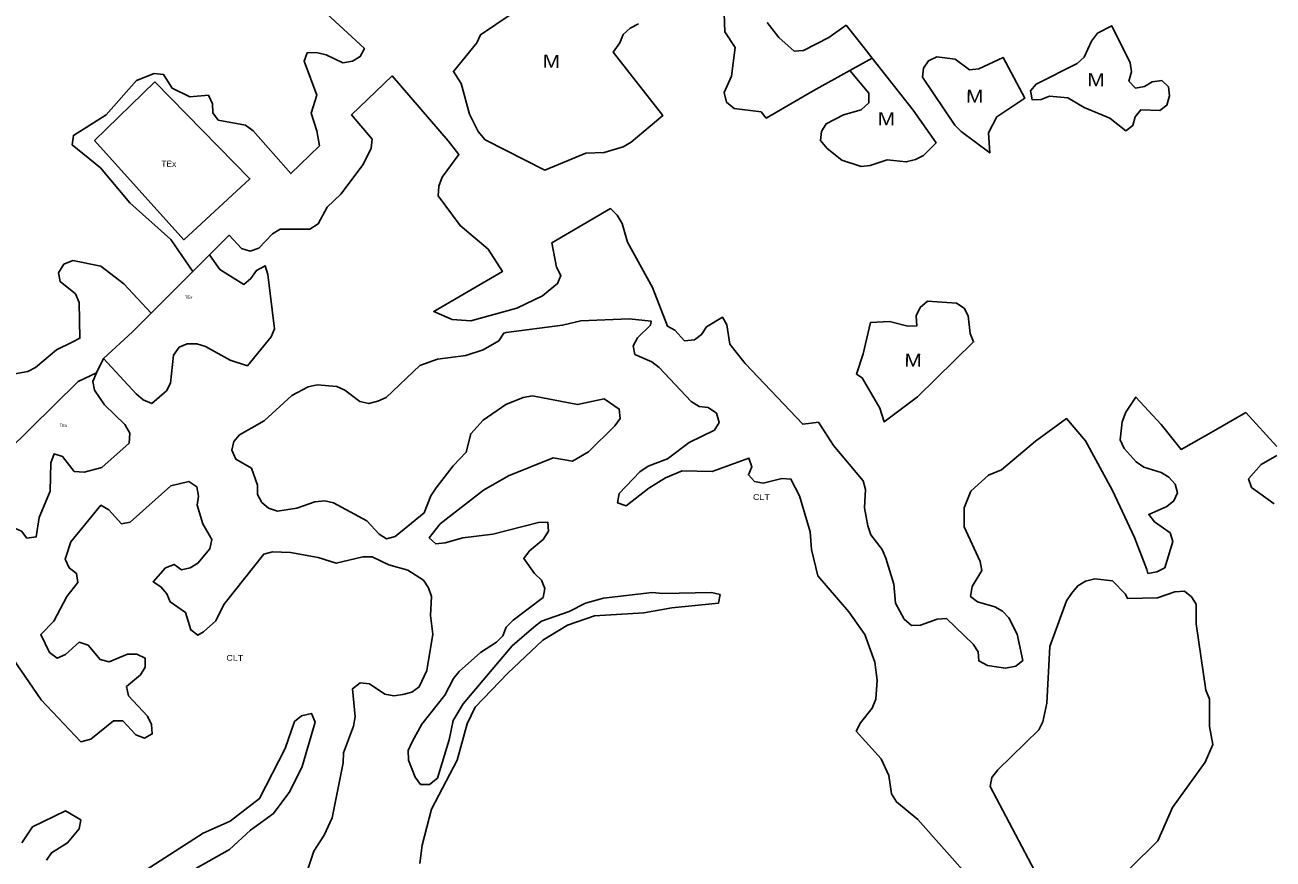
# Model space of a CAD drawing. Extents: x 713589 to 726391, y 7177764 to 7191819.
# Drawn here: x 717161 to 718159, y 7179535 to 7180202 of the extents above; entities that cross this region are included whole.
import ezdxf
from ezdxf.enums import TextEntityAlignment as Align

# ---------------------------------------------------------------- set-up
doc = ezdxf.new("R2010")
doc.units = 0
doc.header["$LTSCALE"] = 2.6
doc.layers.add('63', color=7, linetype='Continuous', lineweight=25)

msp = doc.modelspace()

# ---------------------------------------------------------------- linework, layer by layer
at = {"layer": '63'}
for p, q in [((717838.11, 7180175.6), (717820.18, 7180165.69)), ((717308.17, 7180018.29), (717294.81, 7180004.94)), ((717217.73, 7179923.86), (717223.34, 7179935.43))]:
    msp.add_line(p, q, dxfattribs=at)
for points in [[(717391.45, 7180220.65), (717432.03, 7180183.18), (717428.63, 7180176.88), (717422.38, 7180173.26), (717414.81, 7180171.94), (717401.32, 7180178.2), (717393.42, 7180180.17), (717386.18, 7180179.84), (717383.88, 7180173.26), (717394.07, 7180145.95), (717389.46, 7180131.47), (717394.07, 7180117.32), (717395.98, 7180105.47), (717380.55, 7180090.65), (717373.16, 7180083.26), (717343.06, 7180117.33), (717336.81, 7180121.94), (717315.09, 7180125.89), (717310.82, 7180131.81), (717310.49, 7180139.05), (717307.2, 7180145.96), (717292.39, 7180144.65), (717278.25, 7180151.61), (717271.33, 7180162.42), (717263.76, 7180163.41), (717249.61, 7180157.82), (717225.59, 7180130.18), (717199.26, 7180113.73), (717198.27, 7180106.17), (717220.97, 7180087.73), (717244.33, 7180059.76), (717277.23, 7180030.47), (717294.81, 7180004.94)], [(717549.45, 7180210.74), (717524.83, 7180194.33), (717521.87, 7180187.77), (717503.27, 7180164.85), (717509.29, 7180155.28), (717516.14, 7180130.79), (717522.95, 7180117.05), (717528.65, 7180110.22), (717576.22, 7180085.99), (717609.16, 7180099.47), (717623.92, 7180100.13), (717639.02, 7180104.72), (717645.26, 7180108.33), (717670.74, 7180129.82), (717631.07, 7180180.46), (717636.41, 7180187.75), (717639.04, 7180194.64), (717644.62, 7180199.56), (717651.18, 7180203.17)], [(717719.77, 7180211.37), (717720.43, 7180196.6), (717728.63, 7180184.12), (717725.67, 7180161.15), (717719.76, 7180148.03), (717721.73, 7180140.48), (717727.64, 7180135.23), (717749.3, 7180132.6), (717753.3, 7180127.63), (717790.85, 7180149.48), (717820.18, 7180165.69)], [(717838.11, 7180175.6), (717831.7, 7180183.73), (717817.32, 7180201.97), (717803.46, 7180191.99), (717783.11, 7180181.82), (717775.89, 7180181.16), (717763.42, 7180192), (717754.23, 7180204.14)], [(717820.18, 7180165.69), (717835.61, 7180147.68), (717835.61, 7180139.8), (717829.37, 7180134.22), (717815.26, 7180130.29), (717801.47, 7180123.07), (717797.54, 7180116.84), (717796.88, 7180109.62), (717802.13, 7180103.38), (717813.94, 7180093.86), (717829.36, 7180088.93), (717836.58, 7180089.59), (717850.04, 7180094.18), (717865.47, 7180092.54), (717872.69, 7180094.51), (717879.25, 7180097.79), (717889.31, 7180107.88), (717870.9, 7180134.02), (717838.11, 7180175.6)], [(717308.17, 7180018.29), (717323.83, 7180033.95), (717333.83, 7180023.28), (717340.74, 7180021.31), (717347.65, 7180023.61), (717358.52, 7180035.12), (717364.77, 7180038.74), (717388.46, 7180038.74), (717395.04, 7180043.02), (717402.29, 7180056.51), (717413.15, 7180066.71), (717430.92, 7180090.4), (717437.5, 7180103.56), (717438.16, 7180110.8), (717421.74, 7180130.2), (717454.2, 7180161.37), (717498.95, 7180109.38), (717507.66, 7180098.55), (717494.1, 7180080.51), (717491.47, 7180073.27), (717491.14, 7180065.38), (717508.57, 7180041.68), (717530.95, 7180022.92), (717542.38, 7180004.89), (717487.5, 7179972.96), (717502.31, 7179966.65), (717517.12, 7179965.33), (717553.97, 7179975.53), (717574.38, 7179985.4), (717586.55, 7179995.27), (717589.19, 7180001.85), (717585.57, 7180008.43), (717581.99, 7180027.94), (717628.85, 7180055.21), (717634.29, 7180049.88), (717638.16, 7180043.24), (717642.46, 7180028.26), (717662.39, 7179992.25), (717674.4, 7179961.11), (717680.38, 7179957.99), (717688.12, 7179949.47), (717696.1, 7179950.14), (717701.68, 7179954.4), (717705.62, 7179960.64), (717718.42, 7179968.51), (717722.03, 7179962.27), (717724.32, 7179946.85), (717734.53, 7179933.88), (717736.47, 7179931.41), (717782.66, 7179882.69), (717789.34, 7179883.57), (717795.17, 7179884.33), (717807.34, 7179865.77), (717830.96, 7179837.54), (717832.93, 7179830.65), (717831.94, 7179815.88), (717834.56, 7179801.44), (717837.19, 7179794.22), (717846.05, 7179782.41), (717849, 7179775.52), (717855.56, 7179754.84), (717856.87, 7179739.74), (717863.76, 7179726.94), (717869.67, 7179721.69), (717876.89, 7179722.02), (717890.01, 7179726.94), (717897.56, 7179727.26), (717918.89, 7179706.91), (717922.83, 7179700.68), (717923.48, 7179693.46), (717930.37, 7179689.84), (717944.81, 7179687.55), (717953.02, 7179689.18), (717958.6, 7179693.78), (717954.01, 7179714.78), (717947.45, 7179727.91), (717942.53, 7179733.16), (717936.29, 7179736.77), (717922.51, 7179740.71), (717916.93, 7179744.98), (717918.24, 7179752.86), (717925.79, 7179765.66), (717924.48, 7179772.88), (717911.69, 7179800.77), (717911.69, 7179815.87), (717916.94, 7179829.33), (717931.31, 7179842.11), (717941.6, 7179846.14), (717968.91, 7179869.26), (717993.63, 7179887.23), (718008.73, 7179869.49), (718030.44, 7179829.67), (718047.88, 7179792.15), (718057.74, 7179766.48)], [(717261.43, 7179971.57), (717239.71, 7179994.93), (717221.29, 7180009.09), (717198.91, 7180013.7), (717191.67, 7180010.74), (717187.39, 7180003.83), (717188.71, 7179996.92), (717200.88, 7179987.04), (717203.84, 7179980.13), (717204.45, 7179951.5), (717198.3, 7179948.47), (717185.71, 7179942.28), (717168.93, 7179928.13), (717162.68, 7179924.84), (717140.63, 7179920.89)], [(717223.34, 7179935.43), (717249.57, 7179907.13), (717255.16, 7179902.2), (717262.07, 7179899.23), (717273.59, 7179909.43), (717276.89, 7179915.69), (717279.19, 7179938.06), (717283.8, 7179944.31), (717290.38, 7179946.95), (717297.95, 7179946.94), (717304.86, 7179944.97), (717324.6, 7179934.11), (717338.42, 7179929.5), (717357.51, 7179952.53), (717360.15, 7179959.11), (717354.89, 7180002.55), (717352.59, 7180009.46), (717345.68, 7180005.84), (717341.07, 7179999.26), (717335.47, 7179994.65), (717316.39, 7180006.5), (717308.17, 7180018.29)], [(717294.81, 7180004.94), (717285.34, 7179995.47), (717261.43, 7179971.57)], [(717261.43, 7179971.57), (717246.59, 7179956.74), (717223.34, 7179935.43)], [(717713.56, 7179891.59), (717706.98, 7179896.2), (717699.74, 7179896.85), (717693.49, 7179900.8), (717667.82, 7179928.12), (717661.9, 7179932.73), (717648.41, 7179938.66), (717647.09, 7179945.57), (717650.39, 7179951.82), (717660.92, 7179962.02), (717661.38, 7179965.21), (717643.87, 7179966.98), (717605.2, 7179965.59), (717590.48, 7179961.92), (717545.52, 7179956.15), (717543.42, 7179955.56), (717539.49, 7179949.53), (717526.98, 7179942.3), (717513.16, 7179937.69), (717490.46, 7179934.73), (717476.3, 7179929.8), (717449.32, 7179904.14), (717442.73, 7179901.18), (717435.49, 7179899.2), (717428.25, 7179900.85), (717416.41, 7179910.07), (717409.83, 7179913.03), (717394.36, 7179914.35), (717387.12, 7179912.7), (717373.96, 7179905.8), (717351.91, 7179885.4), (717332.16, 7179874.21), (717327.55, 7179868.95), (717325.91, 7179862.04), (717329.2, 7179854.8), (717341.7, 7179847.56), (717346.63, 7179834.06), (717346.63, 7179826.5), (717349.92, 7179820.24), (717355.19, 7179815.63), (717362.43, 7179813.33), (717377.89, 7179815.63), (717392.37, 7179820.56), (717400.27, 7179821.55), (717407.18, 7179819.9), (717433.83, 7179805.42), (717443.7, 7179794.89), (717449.63, 7179790.94), (717456.54, 7179792.91), (717479.9, 7179811.99), (717485.17, 7179825.48), (717489.45, 7179831.74), (717502.94, 7179849.5), (717513.48, 7179860.36), (717517.1, 7179875.17), (717526.97, 7179886.03), (717545.07, 7179898.53), (717558.9, 7179904.12), (717566.47, 7179905.43), (717602.33, 7179898.52), (717623.72, 7179903.12), (717635.9, 7179894.89), (717636.55, 7179887.32), (717632.28, 7179881.4), (717611.21, 7179860.67), (717598.38, 7179853.11), (717582.91, 7179855.74), (717547.37, 7179841.6), (717527.29, 7179830.08), (717492.74, 7179803.11), (717483.85, 7179791.92), (717489.11, 7179786.98), (717496.68, 7179787.97), (717510.83, 7179791.91), (717534.86, 7179794.87), (717571.38, 7179804.08), (717578.62, 7179804.41), (717579.28, 7179797.17), (717575, 7179790.59), (717564.14, 7179781.37), (717559.53, 7179775.45), (717568.09, 7179763.27), (717573.68, 7179758.01), (717576.31, 7179751.43), (717574.99, 7179744.19), (717550.97, 7179726.09), (717545.37, 7179720.5), (717542.74, 7179713.59), (717537.8, 7179708.33), (717524.97, 7179700.1), (717507.85, 7179684.97), (717503.24, 7179679.37), (717496.33, 7179665.88), (717477.9, 7179642.85), (717470.33, 7179628.7)], [(717217.73, 7179923.86), (717203.15, 7179916.93), (717145.88, 7179860.67), (717045.83, 7179761.97), (717045.8, 7179761.94), (717012.13, 7179728.72), (717014.24, 7179726.64)], [(717146.63, 7179795.56), (717150.5, 7179800.53), (717157.74, 7179797.24), (717162.02, 7179791.65), (717169.59, 7179792.63), (717171.89, 7179808.1), (717180.78, 7179829.16), (717181.11, 7179851.86), (717183.75, 7179859.1), (717190.66, 7179856.8), (717199.87, 7179844.95), (717207.77, 7179844.29), (717221.92, 7179848.24), (717243.97, 7179867.65), (717244.3, 7179875.54), (717240.35, 7179882.46), (717224.23, 7179898.25), (717216.01, 7179910.1), (717214.69, 7179917.01), (717217.73, 7179923.86)], [(718057.74, 7179766.48), (718058.71, 7179763.34), (718065.93, 7179764.65), (718072.16, 7179767.93), (718078.73, 7179788.93), (718076.44, 7179795.82), (718063.97, 7179804.69), (718059.37, 7179810.59), (718073.81, 7179816.83), (718079.39, 7179821.42), (718082.35, 7179827.98), (718080.38, 7179834.88), (718075.46, 7179840.46), (718069.22, 7179844.07), (718055.44, 7179848.34), (718049.21, 7179852.6), (718039.69, 7179863.43), (718036.41, 7179870.33), (718038.05, 7179884.77), (718041.01, 7179892.31), (718049.05, 7179904.46), (718069.42, 7179882.41), (718085.26, 7179862.61), (718111.11, 7179877.3), (718137.01, 7179892.02), (718161.9, 7179865.05)], [(717916.86, 7179519.04), (717874.74, 7179566.44), (717857.64, 7179580.59), (717853.69, 7179587.17), (717851.39, 7179601.65), (717845.47, 7179615.14), (717825.4, 7179637.2), (717828.69, 7179643.78), (717838.23, 7179655.62), (717841.2, 7179662.86), (717842.19, 7179678), (717840.21, 7179692.48), (717832.32, 7179714.53), (717819.49, 7179732.63), (717794.81, 7179761.59), (717789.55, 7179782.65), (717788.57, 7179796.8), (717780.02, 7179825.43), (717773.11, 7179838.93), (717765.87, 7179839.26), (717751.06, 7179835.64), (717744.15, 7179836.96), (717739.22, 7179842.22), (717741.85, 7179848.8), (717739.55, 7179855.71), (717710.26, 7179844.86), (717686.24, 7179845.52), (717672.74, 7179839.93), (717659.58, 7179831.71), (717641.48, 7179817.56), (717634.57, 7179819.86), (717635.89, 7179827.43), (717652.34, 7179844.54), (717658.92, 7179849.15), (717674.39, 7179855.07), (717691.83, 7179868.23), (717711.91, 7179878.1), (717715.86, 7179884.02), (717713.56, 7179891.59)], [(718161.9, 7179857.81), (718149.39, 7179850.57), (718139.19, 7179839.06), (718141.49, 7179832.15), (718159.59, 7179818.98)], [(717147.85, 7179699.51), (717173.51, 7179662.32), (717205.1, 7179628.75), (717213.32, 7179630.72), (717231.43, 7179645.53), (717238.67, 7179645.53), (717249.19, 7179634.34), (717256.1, 7179631.7), (717262.36, 7179634.99), (717261.7, 7179642.56), (717258.41, 7179649.14), (717243.28, 7179665.6), (717241.63, 7179672.84), (717252.82, 7179682.38), (717256.77, 7179688.3), (717256.77, 7179695.54), (717249.86, 7179698.83), (717242.62, 7179698.83), (717227.81, 7179692.58), (717220.58, 7179694.56), (717211.03, 7179706.08), (717203.8, 7179708.38), (717192.93, 7179698.51), (717186.35, 7179695.55), (717180.1, 7179700.16), (717173.19, 7179714.64), (717183.72, 7179725.17), (717193.93, 7179744.91), (717202.82, 7179756.1), (717201.83, 7179763.34), (717195.91, 7179767.95), (717192.62, 7179774.86), (717197.23, 7179788.68), (717221.26, 7179817.96), (717227.51, 7179814.34), (717237.71, 7179803.15), (717244.62, 7179804.47), (717277.2, 7179833.42), (717291.68, 7179837.04), (717297.93, 7179832.76), (717299.25, 7179825.19), (717298.26, 7179817.95), (717302.86, 7179803.14), (717310.1, 7179790.63), (717308.45, 7179783.06), (717298.91, 7179771.55), (717292.65, 7179767.93), (717285.74, 7179766.29), (717279.82, 7179770.57), (717272.91, 7179767.93), (717263.04, 7179756.75), (717269.29, 7179752.8), (717273.89, 7179747.2), (717276.53, 7179740.62), (717289.03, 7179732.06), (717293.3, 7179718.24), (717298.9, 7179713.96), (717303.4, 7179716.71), (717313.05, 7179725.48), (717319.63, 7179738.64), (717351.56, 7179778.78), (717358.47, 7179780.75), (717372.95, 7179780.09), (717395, 7179776.14), (717409.48, 7179771.53), (717430.87, 7179776.79), (717438.11, 7179776.79), (717451.6, 7179770.21), (717466.73, 7179765.93), (717479.24, 7179758.03), (717483.18, 7179751.77), (717485.81, 7179744.86), (717484.82, 7179729.72), (717486.8, 7179714.92), (717481.86, 7179685.63)], [(717973.01, 7179516.23), (717932.66, 7179593.03), (717933.97, 7179600.25), (717938.56, 7179606.16), (717971.39, 7179638.31), (717974.67, 7179644.55), (717977.96, 7179659.64), (717980.26, 7179704.93), (717993.72, 7179741.36), (717997.66, 7179747.27), (718002.59, 7179753.5), (718008.82, 7179757.11), (718016.37, 7179759.08), (718030.48, 7179757.43), (718040.65, 7179746.93), (718042.49, 7179743.26), (718066.25, 7179743.97), (718080.37, 7179748.56), (718087.91, 7179749.22), (718093.49, 7179744.62), (718097.43, 7179738.71), (718097.43, 7179722.96), (718104.97, 7179670.12), (718107.92, 7179662.9), (718107.91, 7179640.91), (718110.54, 7179626.47), (718104.63, 7179612.36), (718078.37, 7179576.27), (718066.55, 7179549.36), (718044.23, 7179527.37)], [(717470.33, 7179628.7), (717467.04, 7179621.79), (717467.36, 7179613.89), (717472.63, 7179600.4), (717476.9, 7179594.48), (717484.14, 7179594.48), (717490.4, 7179599.74), (717499.94, 7179630.34), (717502.91, 7179645.81), (717511.14, 7179658.97), (717550.31, 7179705.36), (717567.42, 7179720.5), (717573.67, 7179725.1), (717595.72, 7179733), (717608.89, 7179739.57), (717623.37, 7179743.52), (717662.2, 7179748.12), (717670.75, 7179747.46), (717709.58, 7179748.11), (717716.49, 7179746.47), (717715.18, 7179739.56), (717677.99, 7179735.94), (717655.61, 7179732), (717616.12, 7179729.37), (717594.4, 7179722.14), (717574.66, 7179709.96), (717546.68, 7179683.64), (717520.68, 7179656.34), (717514.1, 7179643.17), (717506.19, 7179613.89), (717485.78, 7179574.73), (717478.21, 7179546.1)], [(717481.86, 7179685.63), (717475.93, 7179672.8), (717470.01, 7179668.52), (717462.77, 7179666.55), (717455.53, 7179665.56), (717448.29, 7179666.88), (717436.11, 7179675.11), (717428.54, 7179675.77), (717422.62, 7179671.16), (717424.59, 7179648.78), (717423.27, 7179641.22), (717415.37, 7179619.83), (717415.04, 7179611.93), (717406.15, 7179567.84), (717399.89, 7179554.02), (717391.66, 7179541.18), (717386.07, 7179524.4)], [(717297.22, 7179527.38), (717324.21, 7179542.51), (717340.99, 7179557.97), (717359.42, 7179571.46), (717372.26, 7179588.9), (717382.13, 7179608.97), (717392.67, 7179644.51), (717389.71, 7179651.42), (717381.81, 7179649.45), (717376.22, 7179644.84), (717368.64, 7179623.46), (717348.23, 7179583.31), (717324.54, 7179565.22), (717303.15, 7179555.68), (717253.78, 7179523.77)], [(717177.77, 7179533.98), (717181.72, 7179539.9), (717194.55, 7179547.8), (717203.77, 7179558.99), (717205.09, 7179566.23), (717192.91, 7179573.47), (717166.58, 7179560.64)], [(717166.58, 7179560.64), (717158.03, 7179547.81)], [(717478.21, 7179546.1), (717476.23, 7179531.3)]]:
    msp.add_lwpolyline(points, dxfattribs=at)
for points in [[(718046.77, 7180121.75), (718048.41, 7180128.66), (718053.02, 7180134.25), (718068.16, 7180133.59), (718073.75, 7180137.87), (718076.06, 7180145.43), (718075.07, 7180152.67), (718069.81, 7180157.61), (718062.24, 7180156.62), (718055.99, 7180153.01), (718048.75, 7180151.69), (718043.48, 7180157.29), (718045.46, 7180164.53), (718044.47, 7180171.77), (718029.78, 7180201.54), (718018.48, 7180195.46), (718013.54, 7180189.21), (718007.62, 7180176.38), (718002.02, 7180171.44), (717969.44, 7180154.67), (717964.83, 7180149.4), (717965.28, 7180146.91), (717966.15, 7180142.16), (717973.39, 7180142.49), (717979.97, 7180145.12), (717994.78, 7180143.8), (718007.61, 7180136.23), (718028.34, 7180127.67), (718041.17, 7180117.47)], [(717878.29, 7180160.28), (717904.28, 7180122.1), (717909.22, 7180116.83), (717932.25, 7180099.72), (717931.26, 7180115.84), (717937.85, 7180128.68), (717960.37, 7180143.65), (717942.85, 7180176.2), (717923.37, 7180167.18), (717916.13, 7180166.19), (717904.62, 7180174.75), (717889.81, 7180176.73), (717883.23, 7180173.44), (717879.28, 7180167.52)], [(717264.37, 7180156.71), (717216.21, 7180109.84), (717287.47, 7180030.31), (717340.38, 7180079.09)], [(717915, 7179969.46), (717916.64, 7179955.35), (717919.32, 7179948.56), (717874.48, 7179904.72), (717847.76, 7179884.61), (717844.2, 7179895.51), (717830.05, 7179919.87), (717825.6, 7179922.8), (717831.04, 7179938.95), (717836.92, 7179964.18), (717851.99, 7179964.88), (717866.76, 7179961.26), (717873.98, 7179961.59), (717873.32, 7179969.47), (717876.6, 7179976.03), (717882.51, 7179981.28), (717905.48, 7179979.64), (717911.72, 7179975.7)]]:
    msp.add_lwpolyline(points, close=True, dxfattribs=at)

# ---------------------------------------------------------------- texts
for s, height, width, p in [('M', 10.4, 1.2, (717581.48, 7180167.87)), ('M', 10.4, 1.2, (718017.13, 7180153.1)), ('M', 10.4, 1.2, (717920.11, 7180139.99)), ('M', 10.4, 1.2, (717849.43, 7180121.84)), ('TEx', 4.8, 1.05, (717275.52, 7180088.68)), ('TEx', 2.4, 1.05, (717291.38, 7179983.17)), ('M', 10.4, 1.2, (717870.81, 7179928.75)), ('TEx', 2.4, 1.05, (717191.11, 7179880.65)), ('CLT', 4.64, 1.15, (717749.56, 7179822.11)), ('CLT', 4.64, 1.15, (717328.34, 7179693.49))]:
    msp.add_text(s, height=height, rotation=359.062, dxfattribs=dict(at, width=width)).set_placement(p, align=Align.CENTER)

doc.saveas('drawing.dxf')
